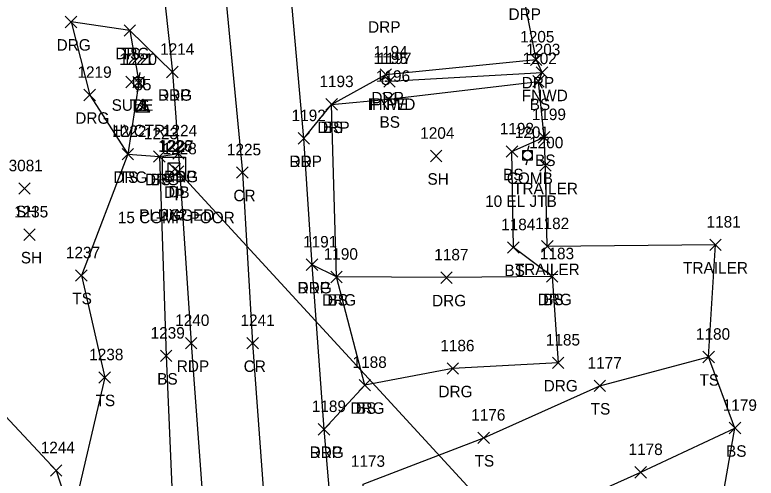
# Model space of a CAD drawing. Extents: x 1461855 to 1464118, y 556196 to 557441.
# Drawn here: x 1462372.6 to 1462501.7, y 556504.3 to 556585 of the extents above; entities that cross this region are included whole.
import ezdxf

# ---------------------------------------------------------------- set-up
doc = ezdxf.new("R2010")
doc.units = 0
for name, color, linetype in [('C_A', 7, 'Continuous'), ('C_I', 7, 'Continuous'), ('CPSM', 7, 'Continuous'), ('D_A', 7, 'Continuous'), ('D_C', 7, 'Continuous'), ('D_I', 7, 'Continuous'), ('D_TIC', 7, 'Continuous'), ('DCP', 7, 'Continuous'), ('DS', 7, 'Continuous'), ('L_A', 7, 'Continuous'), ('L_I', 7, 'Continuous'), ('L_TIC', 7, 'Continuous'), ('LBC', 7, 'Continuous'), ('LELB', 7, 'Continuous'), ('LFNC', 7, 'Continuous'), ('LSOGP', 7, 'Continuous'), ('M_A', 7, 'Continuous'), ('M_I', 7, 'Continuous'), ('MPIP', 7, 'Continuous'), ('P_A', 7, 'Continuous'), ('P_I', 7, 'Continuous'), ('P_TIC', 7, 'Continuous'), ('PET', 7, 'Continuous'), ('PRC', 7, 'Continuous'), ('R_A', 7, 'Continuous'), ('R_I', 7, 'Continuous'), ('R_TIC', 7, 'Continuous'), ('RDG', 7, 'Continuous'), ('RDP', 7, 'Continuous'), ('U_A', 7, 'Continuous'), ('U_C', 7, 'Continuous'), ('U_I', 7, 'Continuous'), ('U_TIC', 7, 'Continuous'), ('ULP', 7, 'Continuous'), ('UP', 7, 'Continuous')]:
    doc.layers.add(name, color=color, linetype=linetype)

msp = doc.modelspace()

# ---------------------------------------------------------------- linework, layer by layer
at = {"layer": 'CPSM'}
for p, q in [((1462393.61, 556568.15), (1462394.86, 556570.32)), ((1462396.11, 556568.15), (1462394.86, 556570.32)), ((1462394.86, 556568.87), (1462394.86, 556570.32)), ((1462393.61, 556568.15), (1462394.86, 556568.87)), ((1462393.61, 556568.15), (1462396.11, 556568.15)), ((1462394.86, 556568.87), (1462394.86, 556568.87)), ((1462394.86, 556568.87), (1462396.11, 556568.15))]:
    msp.add_line(p, q, dxfattribs=at)
at = {"layer": 'D_TIC'}
for points in [[(1462399.46, 556557.15), (1462401.46, 556559.15)], [(1462401.46, 556557.15), (1462399.46, 556559.15)], [(1462400.02, 556556.73), (1462402.02, 556558.73)], [(1462402.02, 556556.73), (1462400.02, 556558.73)]]:
    msp.add_lwpolyline(points, dxfattribs=at)
at = {"layer": 'DCP'}
msp.add_lwpolyline([(1462485.78, 556465.55), (1462401.02, 556557.73)], dxfattribs=at)
at = {"layer": 'DS'}
for p, q in [((1462398.28, 556560.22), (1462402.28, 556560.22)), ((1462398.28, 556556.22), (1462398.28, 556560.22)), ((1462402.28, 556560.22), (1462402.28, 556556.22)), ((1462399.28, 556557.22), (1462399.28, 556559.22)), ((1462399.28, 556559.22), (1462401.28, 556559.22)), ((1462401.28, 556559.22), (1462401.28, 556557.22)), ((1462400.29, 556558.22), (1462400.29, 556558.22)), ((1462400.29, 556558.22), (1462400.29, 556558.22)), ((1462402.28, 556556.22), (1462398.28, 556556.22)), ((1462401.28, 556557.22), (1462399.28, 556557.22))]:
    msp.add_line(p, q, dxfattribs=at)
at = {"layer": 'L_TIC'}
for points in [[(1462391.6, 556581.28), (1462393.6, 556583.28)], [(1462393.6, 556581.28), (1462391.6, 556583.28)], [(1462463.38, 556573.98), (1462465.38, 556575.98)], [(1462465.38, 556573.98), (1462463.38, 556575.98)], [(1462393.16, 556572.28), (1462395.16, 556574.28)], [(1462395.16, 556572.28), (1462393.16, 556574.28)], [(1462436.83, 556572.45), (1462438.83, 556574.45)], [(1462438.83, 556572.45), (1462436.83, 556574.45)], [(1462462.77, 556572.43), (1462464.77, 556574.43)], [(1462464.77, 556572.43), (1462462.77, 556574.43)], [(1462426.75, 556568.43), (1462428.75, 556570.43)], [(1462428.75, 556568.43), (1462426.75, 556570.43)], [(1462436.64, 556569.36), (1462438.64, 556571.36)], [(1462438.64, 556569.36), (1462436.64, 556571.36)], [(1462463.73, 556562.69), (1462465.73, 556564.69)], [(1462465.73, 556562.69), (1462463.73, 556564.69)], [(1462391.25, 556559.75), (1462393.25, 556561.75)], [(1462393.25, 556559.75), (1462391.25, 556561.75)], [(1462444.94, 556559.44), (1462446.94, 556561.44)], [(1462446.94, 556559.44), (1462444.94, 556561.44)], [(1462458.14, 556560.21), (1462460.14, 556562.21)], [(1462460.14, 556560.21), (1462458.14, 556562.21)], [(1462396.76, 556559.35), (1462398.76, 556561.35)], [(1462398.76, 556559.35), (1462396.76, 556561.35)], [(1462463.98, 556557.78), (1462465.98, 556559.78)], [(1462465.98, 556557.78), (1462463.98, 556559.78)], [(1462373.28, 556553.78), (1462375.28, 556555.78)], [(1462375.28, 556553.78), (1462373.28, 556555.78)], [(1462374.14, 556545.74), (1462376.14, 556547.74)], [(1462376.14, 556545.74), (1462374.14, 556547.74)], [(1462493.58, 556543.98), (1462495.58, 556545.98)], [(1462495.58, 556543.98), (1462493.58, 556545.98)], [(1462458.39, 556543.52), (1462460.39, 556545.52)], [(1462460.39, 556543.52), (1462458.39, 556545.52)], [(1462464.29, 556543.7), (1462466.29, 556545.7)], [(1462466.29, 556543.7), (1462464.29, 556545.7)], [(1462383.18, 556538.63), (1462385.18, 556540.63)], [(1462385.18, 556538.63), (1462383.18, 556540.63)], [(1462427.58, 556538.38), (1462429.58, 556540.38)], [(1462429.58, 556538.38), (1462427.58, 556540.38)], [(1462465.13, 556538.46), (1462467.13, 556540.46)], [(1462467.13, 556538.46), (1462465.13, 556540.46)], [(1462397.93, 556524.64), (1462399.93, 556526.64)], [(1462399.93, 556524.64), (1462397.93, 556526.64)], [(1462492.38, 556524.45), (1462494.38, 556526.45)], [(1462494.38, 556524.45), (1462492.38, 556526.45)], [(1462387.23, 556520.88), (1462389.23, 556522.88)], [(1462389.23, 556520.88), (1462387.23, 556522.88)], [(1462432.52, 556519.55), (1462434.52, 556521.55)], [(1462434.52, 556519.55), (1462432.52, 556521.55)], [(1462473.43, 556519.42), (1462475.43, 556521.42)], [(1462475.43, 556519.42), (1462473.43, 556521.42)], [(1462496.97, 556512.07), (1462498.97, 556514.07)], [(1462498.97, 556512.07), (1462496.97, 556514.07)], [(1462453.22, 556510.37), (1462455.22, 556512.37)], [(1462455.22, 556510.37), (1462453.22, 556512.37)], [(1462480.56, 556504.37), (1462482.56, 556506.37)], [(1462482.56, 556504.37), (1462480.56, 556506.37)]]:
    msp.add_lwpolyline(points, dxfattribs=at)
at = {"layer": 'LBC'}
msp.add_lwpolyline([(1462494.58, 556544.98), (1462465.29, 556544.7), (1462464.98, 556558.78)], dxfattribs=at)
at = {"layer": 'LELB'}
for points in [[(1462392.6, 556582.28), (1462394.16, 556573.28), (1462392.25, 556560.75), (1462384.18, 556539.63), (1462388.23, 556521.88), (1462382.5, 556497.28), (1462381.8, 556477.79), (1462382.84, 556464.06), (1462375.48, 556459.39)], [(1462433.52, 556520.55), (1462428.58, 556539.38), (1462427.75, 556569.43), (1462437.64, 556570.36), (1462463.77, 556573.43)], [(1462466.13, 556539.46), (1462459.39, 556544.52), (1462459.14, 556561.21), (1462464.73, 556563.69)], [(1462397.76, 556560.35), (1462398.93, 556525.64), (1462400.26, 556494.74), (1462403.17, 556466), (1462397.35, 556446.97), (1462388.69, 556445.8), (1462367.43, 556444.36), (1462357.72, 556443.74), (1462341.15, 556446.51)], [(1462439.15, 556431.13), (1462435.99, 556449.46), (1462432.95, 556481.6), (1462433.21, 556503.32), (1462454.22, 556511.37), (1462474.43, 556520.42), (1462493.38, 556525.45)], [(1462442.19, 556448.55), (1462441.37, 556472.71), (1462438.72, 556493.88), (1462458.62, 556495.04), (1462481.56, 556505.37), (1462497.97, 556513.07)]]:
    msp.add_lwpolyline(points, dxfattribs=at)
at = {"layer": 'LFNC'}
msp.add_lwpolyline([(1462437.83, 556573.45), (1462464.38, 556574.98)], dxfattribs=at)
at = {"layer": 'LSOGP'}
msp.add_lwpolyline([(1462492.96, 556484.56), (1462497.97, 556513.07), (1462493.38, 556525.45), (1462494.58, 556544.98), (1462465.29, 556544.7), (1462464.98, 556558.78), (1462464.73, 556563.69), (1462463.77, 556573.43), (1462464.38, 556574.98), (1462463.35, 556577.21), (1462461.05, 556589.14), (1462458.64, 556594.55), (1462463.25, 556608.89), (1462457.67, 556620.06), (1462462.6, 556634.11), (1462467.83, 556647.65), (1462473.08, 556660.82), (1462473.46, 556663.65), (1462459.32, 556677.13), (1462457.71, 556687.22)], dxfattribs=at)
at = {"layer": 'MPIP'}
for radius in [0.625, 0.0833]:
    msp.add_circle((1462437.19, 556573.47), radius, dxfattribs=at)
at = {"layer": 'P_TIC'}
for points in [[(1462399.02, 556574.06), (1462401.02, 556576.06)], [(1462401.02, 556574.06), (1462399.02, 556576.06)], [(1462421.91, 556562.51), (1462423.91, 556564.51)], [(1462423.91, 556562.51), (1462421.91, 556564.51)], [(1462400.08, 556559.86), (1462402.08, 556561.86)], [(1462402.08, 556559.86), (1462400.08, 556561.86)], [(1462411.2, 556556.56), (1462413.2, 556558.56)], [(1462413.2, 556556.56), (1462411.2, 556558.56)], [(1462423.33, 556540.51), (1462425.33, 556542.51)], [(1462425.33, 556540.51), (1462423.33, 556542.51)], [(1462402.29, 556526.85), (1462404.29, 556528.85)], [(1462404.29, 556526.85), (1462402.29, 556528.85)], [(1462412.99, 556526.84), (1462414.99, 556528.84)], [(1462414.99, 556526.84), (1462412.99, 556528.84)], [(1462425.42, 556511.86), (1462427.42, 556513.86)], [(1462427.42, 556511.86), (1462425.42, 556513.86)]]:
    msp.add_lwpolyline(points, dxfattribs=at)
at = {"layer": 'PET'}
for points in [[(1462450, 556394.49), (1462444.86, 556401.11), (1462442.31, 556410.09), (1462435.59, 556433.02), (1462433.05, 556445.21), (1462429.15, 556480.97), (1462426.42, 556512.86), (1462424.33, 556541.51), (1462422.91, 556563.51), (1462420.11, 556594.82)], [(1462398.06, 556593.15), (1462400.02, 556575.06), (1462401.08, 556560.86), (1462403.29, 556527.85), (1462406.05, 556490.12), (1462407.3, 556463.05), (1462405.84, 556453.02), (1462399.79, 556444.3), (1462382.48, 556434.45)]]:
    msp.add_lwpolyline(points, dxfattribs=at)
at = {"layer": 'PRC'}
msp.add_lwpolyline([(1462408.92, 556592.16), (1462412.2, 556557.56), (1462413.99, 556527.84), (1462417.1, 556485.33), (1462418.69, 556452.73), (1462415.65, 556430.87), (1462414.08, 556417.65)], dxfattribs=at)
at = {"layer": 'R_TIC'}
for points in [[(1462381.37, 556582.78), (1462383.37, 556584.78)], [(1462383.37, 556582.78), (1462381.37, 556584.78)], [(1462391.6, 556581.28), (1462393.6, 556583.28)], [(1462393.6, 556581.28), (1462391.6, 556583.28)], [(1462462.35, 556576.21), (1462464.35, 556578.21)], [(1462464.35, 556576.21), (1462462.35, 556578.21)], [(1462399.02, 556574.06), (1462401.02, 556576.06)], [(1462401.02, 556574.06), (1462399.02, 556576.06)], [(1462436.17, 556573.6), (1462438.17, 556575.6)], [(1462438.17, 556573.6), (1462436.17, 556575.6)], [(1462384.62, 556570.05), (1462386.62, 556572.05)], [(1462386.62, 556570.05), (1462384.62, 556572.05)], [(1462426.75, 556568.43), (1462428.75, 556570.43)], [(1462428.75, 556568.43), (1462426.75, 556570.43)], [(1462421.91, 556562.51), (1462423.91, 556564.51)], [(1462423.91, 556562.51), (1462421.91, 556564.51)], [(1462391.25, 556559.75), (1462393.25, 556561.75)], [(1462393.25, 556559.75), (1462391.25, 556561.75)], [(1462400.08, 556559.86), (1462402.08, 556561.86)], [(1462402.08, 556559.86), (1462400.08, 556561.86)], [(1462396.76, 556559.35), (1462398.76, 556561.35)], [(1462398.76, 556559.35), (1462396.76, 556561.35)], [(1462423.33, 556540.51), (1462425.33, 556542.51)], [(1462425.33, 556540.51), (1462423.33, 556542.51)], [(1462427.58, 556538.38), (1462429.58, 556540.38)], [(1462429.58, 556538.38), (1462427.58, 556540.38)], [(1462446.75, 556538.26), (1462448.75, 556540.26)], [(1462448.75, 556538.26), (1462446.75, 556540.26)], [(1462465.13, 556538.46), (1462467.13, 556540.46)], [(1462467.13, 556538.46), (1462465.13, 556540.46)], [(1462465.13, 556538.46), (1462467.13, 556540.46)], [(1462467.13, 556538.46), (1462465.13, 556540.46)], [(1462466.17, 556523.44), (1462468.17, 556525.44)], [(1462468.17, 556523.44), (1462466.17, 556525.44)], [(1462447.85, 556522.43), (1462449.85, 556524.43)], [(1462449.85, 556522.43), (1462447.85, 556524.43)], [(1462432.52, 556519.55), (1462434.52, 556521.55)], [(1462434.52, 556519.55), (1462432.52, 556521.55)], [(1462425.42, 556511.86), (1462427.42, 556513.86)], [(1462427.42, 556511.86), (1462425.42, 556513.86)], [(1462378.79, 556504.69), (1462380.79, 556506.69)], [(1462380.79, 556504.69), (1462378.79, 556506.69)]]:
    msp.add_lwpolyline(points, dxfattribs=at)
at = {"layer": 'RDG'}
for points in [[(1462339.36, 556595.74), (1462349.96, 556573.72), (1462350.64, 556554.62), (1462363.11, 556531.92), (1462365.3, 556525.05), (1462369.29, 556516.9), (1462379.79, 556505.69), (1462382.5, 556497.28), (1462387.1, 556495.6), (1462388.91, 556495.94), (1462400.26, 556494.74), (1462406.05, 556490.12)], [(1462400.02, 556575.06), (1462392.6, 556582.28), (1462382.37, 556583.78), (1462385.62, 556571.05), (1462392.25, 556560.75), (1462397.76, 556560.35), (1462401.08, 556560.86)], [(1462466.13, 556539.46), (1462447.75, 556539.26), (1462428.58, 556539.38), (1462424.33, 556541.51)], [(1462466.13, 556539.46), (1462467.17, 556524.44), (1462448.85, 556523.43), (1462433.52, 556520.55), (1462426.42, 556512.86)]]:
    msp.add_lwpolyline(points, dxfattribs=at)
at = {"layer": 'RDP'}
msp.add_lwpolyline([(1462422.91, 556563.51), (1462427.75, 556569.43), (1462437.17, 556574.6), (1462463.35, 556577.21)], dxfattribs=at)
at = {"layer": 'U_TIC'}
for points in [[(1462391.9, 556572.31), (1462393.9, 556574.31)], [(1462393.9, 556572.31), (1462391.9, 556574.31)]]:
    msp.add_lwpolyline(points, dxfattribs=at)
at = {"layer": 'ULP'}
for p, q in [((1462394.33, 556574.95), (1462394.16, 556574.11)), ((1462393.33, 556572.45), (1462393.33, 556574.11)), ((1462393.33, 556574.11), (1462394.99, 556574.11)), ((1462394.16, 556573.28), (1462394.16, 556573.28)), ((1462394.99, 556574.11), (1462394.99, 556572.45)), ((1462394.99, 556572.45), (1462393.33, 556572.45)), ((1462393.91, 556571.61), (1462394.16, 556572.45))]:
    msp.add_line(p, q, dxfattribs=at)
at = {"layer": 'UP'}
for p, q in [((1462461.02, 556559.73), (1462461.02, 556561.4)), ((1462461.02, 556561.4), (1462462.68, 556561.4)), ((1462462.1, 556562.23), (1462461.85, 556561.4)), ((1462462.68, 556561.4), (1462462.68, 556559.73)), ((1462461.85, 556560.57), (1462461.85, 556560.57)), ((1462462.68, 556559.73), (1462461.02, 556559.73)), ((1462461.6, 556558.9), (1462461.85, 556559.73))]:
    msp.add_line(p, q, dxfattribs=at)
msp.add_circle((1462461.85, 556560.57), 0.833, dxfattribs=at)

# ---------------------------------------------------------------- texts
at = {"layer": 'C_A'}
msp.add_text('HVCTRL', height=2, dxfattribs=at).set_placement((1462389.55, 556563.87))
at = {"layer": 'C_I'}
msp.add_text('35', height=2, dxfattribs=at).set_placement((1462393.39, 556571.87))
at = {"layer": 'D_A'}
for s, p in [('DIB', (1462398.56, 556553.15)), ('DI', (1462399.34, 556553.22)), ('P', (1462400.39, 556552.73))]:
    msp.add_text(s, height=2, dxfattribs=at).set_placement(p)
at = {"layer": 'D_C'}
for s, p in [('PLUGGED', (1462394.24, 556549.15)), ('2X2', (1462397.86, 556549.22)), ('15 CGMP POOR', (1462390.52, 556548.73))]:
    msp.add_text(s, height=2, dxfattribs=at).set_placement(p)
at = {"layer": 'D_I'}
for s, p in [('1226', (1462397.54, 556561.22)), ('1227', (1462397.76, 556561.15)), ('1228', (1462398.32, 556560.73))]:
    msp.add_text(s, height=2, dxfattribs=at).set_placement(p)
at = {"layer": 'L_A'}
for s, p in [('TS', (1462391.01, 556577.28)), ('FNWD', (1462460.84, 556569.98)), ('FNWD', (1462434.3, 556568.45)), ('BS', (1462462.22, 556568.43)), ('TS', (1462392.57, 556568.28)), ('BS', (1462436.08, 556565.36)), ('BS', (1462426.19, 556564.43)), ('BS', (1462463.17, 556558.69)), ('TS', (1462390.66, 556555.75)), ('BS', (1462457.59, 556556.21)), ('BS', (1462396.2, 556555.35)), ('SH', (1462444.43, 556555.44)), ('TRAILER', (1462459.34, 556553.78)), ('SH', (1462372.77, 556549.78)), ('SH', (1462373.63, 556541.74)), ('BS', (1462457.83, 556539.52)), ('TRAILER', (1462459.64, 556539.7)), ('TRAILER', (1462488.93, 556539.98)), ('TS', (1462382.59, 556534.63)), ('BS', (1462427.02, 556534.38)), ('BS', (1462464.57, 556534.46)), ('BS', (1462397.37, 556520.64)), ('TS', (1462491.79, 556520.45)), ('TS', (1462386.64, 556516.88)), ('BS', (1462431.96, 556515.55)), ('TS', (1462472.84, 556515.42)), ('BS', (1462496.41, 556508.07)), ('TS', (1462452.63, 556506.37))]:
    msp.add_text(s, height=2, dxfattribs=at).set_placement(p)
at = {"layer": 'L_I'}
for s, p in [('1203', (1462461.61, 556577.98)), ('1220', (1462391.38, 556576.28)), ('1197', (1462435.71, 556576.45)), ('1202', (1462461, 556576.43)), ('1193', (1462425.62, 556572.43)), ('1196', (1462435.46, 556573.36)), ('1199', (1462462.59, 556566.69)), ('1222', (1462389.55, 556563.75)), ('1223', (1462395.06, 556563.35)), ('1204', (1462443.17, 556563.44)), ('1198', (1462457.02, 556564.21)), ('1200', (1462462.13, 556561.78)), ('3081', (1462371.51, 556557.78)), ('1235', (1462372.45, 556549.74)), ('1181', (1462493.02, 556547.98)), ('1184', (1462457.26, 556547.52)), ('1182', (1462463.16, 556547.7)), ('1237', (1462381.48, 556542.63)), ('1190', (1462426.37, 556542.38)), ('1183', (1462464.01, 556542.46)), ('1239', (1462396.23, 556528.64)), ('1180', (1462491.17, 556528.45)), ('1238', (1462385.54, 556524.88)), ('1188', (1462431.39, 556523.55)), ('1177', (1462472.31, 556523.42)), ('1179', (1462495.84, 556516.07)), ('1176', (1462452.04, 556514.37)), ('1178', (1462479.43, 556508.37)), ('1173', (1462431.09, 556506.32))]:
    msp.add_text(s, height=2, dxfattribs=at).set_placement(p)
at = {"layer": 'M_A'}
msp.add_text('IPIPE', height=2, dxfattribs=at).set_placement((1462434.02, 556568.47))
at = {"layer": 'M_I'}
msp.add_text('1195', height=2, dxfattribs=at).set_placement((1462435.06, 556576.47))
at = {"layer": 'P_A'}
for s, p in [('RDP', (1462397.51, 556570.06)), ('RDP', (1462420.4, 556558.51)), ('RDP', (1462398.57, 556555.86)), ('CR', (1462410.64, 556552.56)), ('RDP', (1462421.81, 556536.51)), ('RDP', (1462400.78, 556522.85)), ('CR', (1462412.43, 556522.84)), ('RDP', (1462423.91, 556507.86))]:
    msp.add_text(s, height=2, dxfattribs=at).set_placement(p)
at = {"layer": 'P_I'}
for s, p in [('1214', (1462397.89, 556578.06)), ('1192', (1462420.78, 556566.51)), ('1224', (1462398.38, 556563.86)), ('1225', (1462409.51, 556560.56)), ('1191', (1462422.77, 556544.51)), ('1240', (1462400.51, 556530.85)), ('1241', (1462411.87, 556530.84)), ('1189', (1462424.29, 556515.86))]:
    msp.add_text(s, height=2, dxfattribs=at).set_placement(p)
at = {"layer": 'R_A'}
for s, p in [('DRP', (1462458.54, 556584.14)), ('DRP', (1462434.09, 556581.9)), ('DRG', (1462379.86, 556578.78)), ('DRG', (1462390.09, 556577.28)), ('DRP', (1462460.84, 556572.21)), ('DRG', (1462397.51, 556570.06)), ('DRP', (1462434.66, 556569.6)), ('DRG', (1462383.11, 556566.05)), ('DRP', (1462425.24, 556564.43)), ('DRP', (1462420.4, 556558.51)), ('DRG', (1462389.73, 556555.75)), ('DRG', (1462398.57, 556555.86)), ('DRG', (1462395.24, 556555.35)), ('DRG', (1462421.81, 556536.51)), ('DRG', (1462426.07, 556534.38)), ('DRG', (1462445.23, 556534.26)), ('DRG', (1462463.62, 556534.46)), ('DRG', (1462463.62, 556534.46)), ('DRG', (1462464.66, 556519.44)), ('DRG', (1462446.34, 556518.43)), ('DRG', (1462431.01, 556515.55)), ('DRG', (1462423.91, 556507.86))]:
    msp.add_text(s, height=2, dxfattribs=at).set_placement(p)
at = {"layer": 'R_I'}
for s, p in [('1205', (1462460.58, 556580.21)), ('1214', (1462397.89, 556578.06)), ('1194', (1462435.04, 556577.6)), ('1219', (1462383.49, 556574.05)), ('1193', (1462425.62, 556572.43)), ('1192', (1462420.78, 556566.51)), ('1222', (1462389.55, 556563.75)), ('1223', (1462395.06, 556563.35)), ('1224', (1462398.38, 556563.86)), ('1191', (1462422.77, 556544.51)), ('1190', (1462426.37, 556542.38)), ('1187', (1462445.62, 556542.26)), ('1183', (1462464.01, 556542.46)), ('1183', (1462464.01, 556542.46)), ('1185', (1462465.04, 556527.44)), ('1186', (1462446.67, 556526.43)), ('1188', (1462431.39, 556523.55)), ('1189', (1462424.29, 556515.86)), ('1244', (1462377.1, 556508.69))]:
    msp.add_text(s, height=2, dxfattribs=at).set_placement(p)
at = {"layer": 'U_A'}
for s, p in [('SUBE', (1462389.44, 556568.31)), ('LI', (1462393.26, 556568.28)), ('COMB', (1462458.24, 556555.57))]:
    msp.add_text(s, height=2, dxfattribs=at).set_placement(p)
at = {"layer": 'U_C'}
msp.add_text('10 EL JTB', height=2, dxfattribs=at).set_placement((1462454.46, 556551.57))
at = {"layer": 'U_I'}
for s, p in [('1221', (1462390.78, 556576.31)), ('1220', (1462391.38, 556576.28)), ('1201', (1462459.64, 556563.57))]:
    msp.add_text(s, height=2, dxfattribs=at).set_placement(p)

doc.saveas('drawing.dxf')
